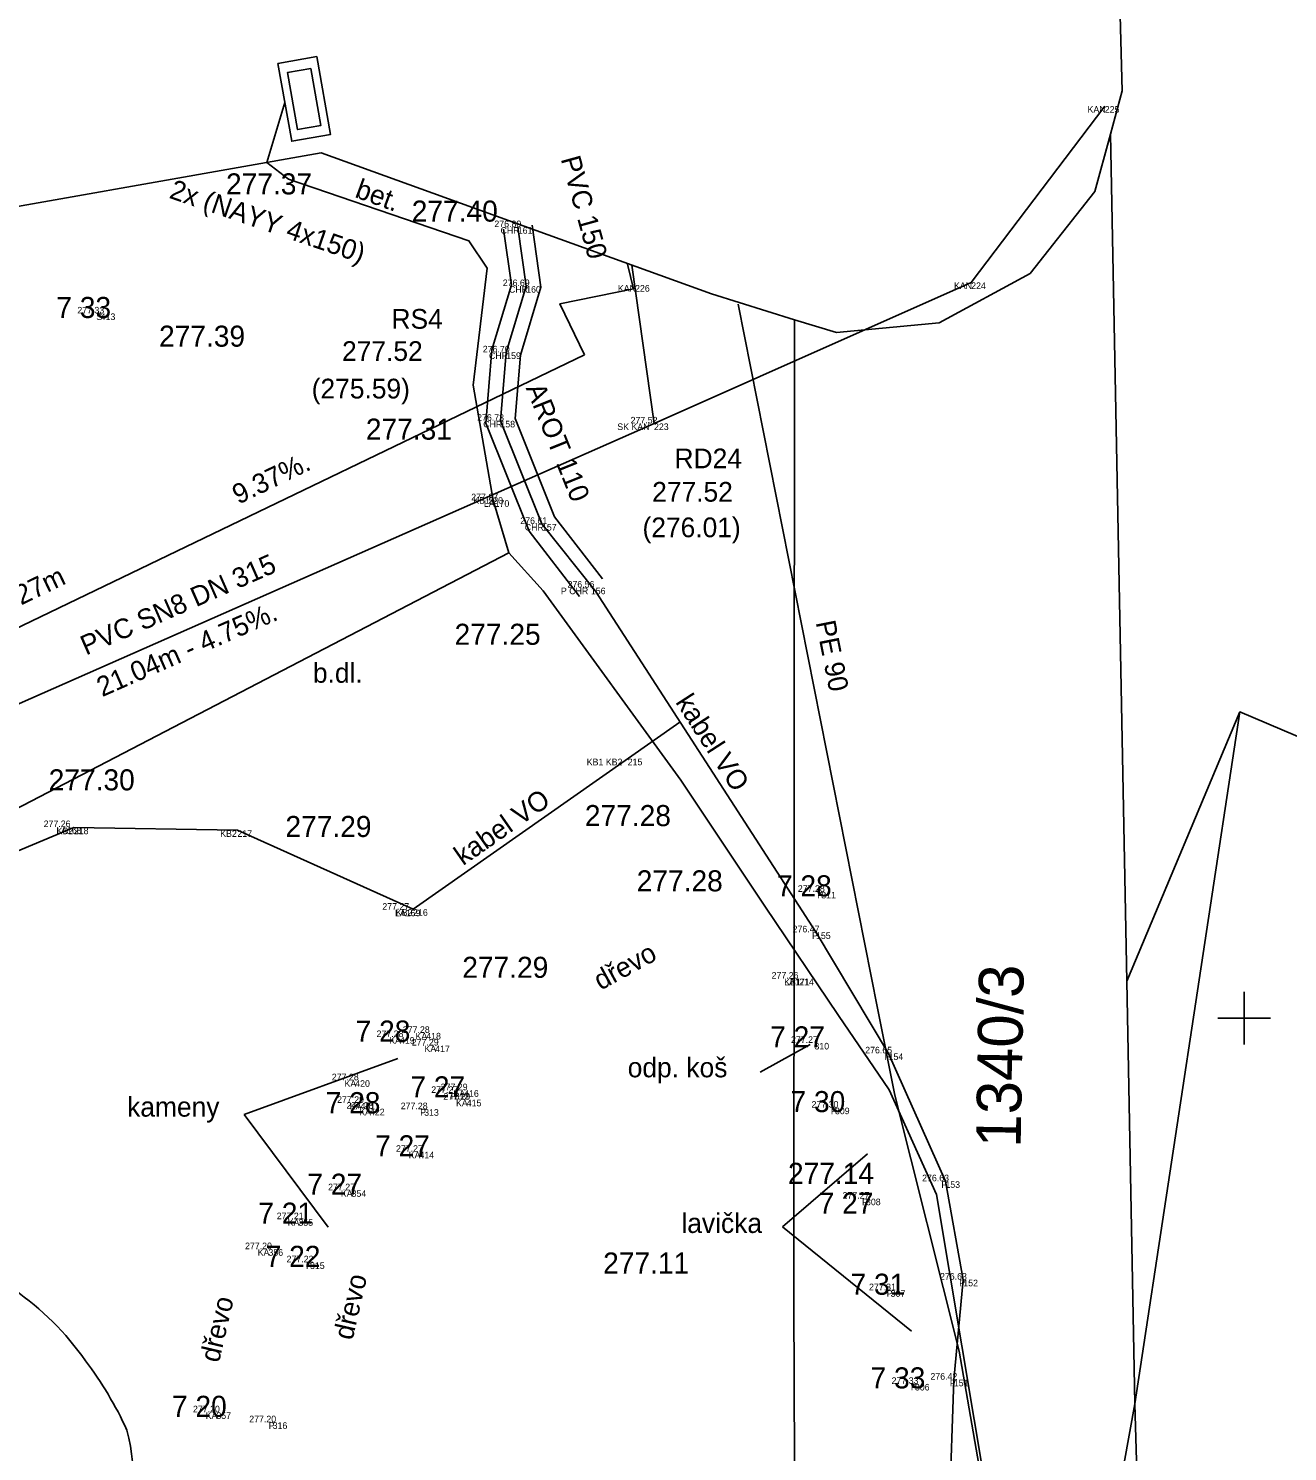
# Model space of a CAD drawing. Extents: x -601602 to -600882, y -1162594 to -1161950.
# Drawn here: x -601173.11 to -601149.18, y -1162033.24 to -1162006.19 of the extents above; entities that cross this region are included whole.
import ezdxf

# ---------------------------------------------------------------- set-up
doc = ezdxf.new("R2010")
doc.units = 0
for name, color, linetype in [('BODY', 7, 'Continuous'), ('BODY_CISLA', 7, 'Continuous'), ('BODY_KODY', 7, 'Continuous'), ('BODY_VYSKY_CELE', 7, 'Continuous'), ('G_TEXTY', 7, 'Continuous'), ('H_KOTY_VYSKOVE', 7, 'Continuous'), ('H_VYSKY_PREVZATE', 7, 'Continuous'), ('IS_CHRÁNIČKY', 7, 'Continuous'), ('IS_EON_NN', 7, 'Continuous'), ('IS_KAN_SPLASKOVA', 7, 'Continuous'), ('IS_ODVODNENI_HDV', 7, 'Continuous'), ('IS_ODVODNĚNÍ', 7, 'Continuous'), ('IS_VO_AREAL', 7, 'Continuous'), ('IS_VODOVOD', 7, 'Continuous'), ('KN_Hranice parcel', 7, 'Continuous'), ('KN_Parcelní čísla', 7, 'Continuous'), ('KN_Vnitřní kresba', 7, 'Continuous'), ('X_SOUR_KRIZKY_SEVER', 7, 'Continuous')]:
    doc.layers.add(name, color=color, linetype=linetype)

# ---------------------------------------------------------------- blocks, each defined once
blk = doc.blocks.new('POINT_DISPLAY')
blk.add_line((0, 0), (0, 0))
blk = doc.blocks.new('132_9')
at = {"layer": 'IS_EON_NN'}
for points in [[(-1.5, 1.5), (1.5, 1.5), (1.5, 0), (-1.5, 0)], [(-1.1, 1.2), (1.1, 1.2), (1.1, 0.3), (-1.1, 0.3)]]:
    blk.add_lwpolyline(points, close=True, dxfattribs=at)

msp = doc.modelspace()

# ---------------------------------------------------------------- linework, layer by layer
at = {"layer": 'G_TEXTY'}
for p, q in [((-601159.199, -1162026.027), (-601158.249, -1162025.499)), ((-601169.011, -1162026.832), (-601166.092, -1162025.768)), ((-601169.011, -1162026.832), (-601167.416, -1162028.971)), ((-601157.161, -1162027.579), (-601158.777, -1162028.963)), ((-601158.777, -1162028.963), (-601156.322, -1162030.951))]:
    msp.add_line(p, q, dxfattribs=at)
at = {"layer": 'IS_CHRÁNIČKY'}
for points in [[(-601162.202, -1162016.652), (-601163.109, -1162015.472), (-601163.86, -1162013.608), (-601163.758, -1162012.402), (-601163.369, -1162011.111), (-601163.538, -1162009.931)], [(-601162.638, -1162016.988), (-601163.591, -1162015.748), (-601164.42, -1162013.692), (-601164.302, -1162012.298), (-601163.931, -1162011.069), (-601164.082, -1162010.009)]]:
    msp.add_lwpolyline(points, dxfattribs=at)
at = {"layer": 'IS_EON_NN'}
for points in [[(-601168.24, -1162007.6), (-601168.58, -1162008.74), (-601168.17, -1162009.06), (-601164.74, -1162010.23), (-601164.39, -1162010.75), (-601164.66, -1162012.97), (-601164.28, -1162015.16), (-601163.98, -1162016.16)], [(-601173.65, -1162020.94), (-601173.38, -1162021.04), (-601163.98, -1162016.16)], [(-601163.98, -1162016.16), (-601163.33, -1162016.88), (-601160.71, -1162020.48), (-601159.11, -1162022.87), (-601157.71, -1162024.95), (-601156.75, -1162026.36), (-601155.85, -1162028.35), (-601154.65, -1162035.5), (-601155.01, -1162041.12), (-601155.31, -1162044.77), (-601156.69, -1162049.18), (-601157.91, -1162051.3), (-601160.19, -1162054.43), (-601160.24, -1162054.96), (-601159.53, -1162057.02), (-601158.24, -1162061.13), (-601156.45, -1162065.9)]]:
    msp.add_lwpolyline(points, dxfattribs=at)
at = {"layer": 'IS_KAN_SPLASKOVA'}
for points in [[(-601162.543, -1162012.396), (-601163.01, -1162011.424), (-601161.61, -1162011.139), (-601161.724, -1162010.674)], [(-601184.326, -1162054.364), (-601187.478, -1162047.498), (-601187.521, -1162033.934), (-601180.812, -1162021.187), (-601162.543, -1162012.396)]]:
    msp.add_lwpolyline(points, dxfattribs=at)
at = {"layer": 'IS_ODVODNENI_HDV'}
msp.add_line((-601161.22, -1162013.7), (-601180.4, -1162022.16), dxfattribs=at)
for centre, radius, start, end in [((-601176.384, -1162034.532), 5.3, 34.7611, 76.4254), ((-601177.686, -1162035.791), 7.094, 24.6751, 37.1246), ((-601173.973, -1162033.607), 2.841, 326.6304, 15.8773)]:
    msp.add_arc(centre, radius, start, end, dxfattribs=at)
at = {"layer": 'IS_ODVODNĚNÍ'}
for points in [[(-601161.22, -1162013.7), (-601155.19, -1162011.02), (-601152.65, -1162007.67)], [(-601161.639, -1162010.695), (-601161.22, -1162013.7)]]:
    msp.add_lwpolyline(points, dxfattribs=at)
at = {"layer": 'IS_VO_AREAL'}
for points in [[(-601164.95, -1162058.87), (-601164.15, -1162057.56), (-601163.04, -1162056.17), (-601161.14, -1162054.03), (-601158.99, -1162051.22), (-601157.56, -1162048.96), (-601156.33, -1162045.65), (-601156.093, -1162044.563), (-601155.26, -1162040.45), (-601155.6, -1162034.28), (-601155.52, -1162031.87), (-601155.34, -1162029.97), (-601155.68, -1162028.1), (-601156.76, -1162025.67), (-601158.14, -1162023.37), (-601162.335, -1162016.886), (-601163.35, -1162015.61), (-601164.14, -1162013.65), (-601164.03, -1162012.35), (-601163.65, -1162011.09), (-601163.81, -1162009.97)], [(-601160.726, -1162019.373), (-601165.8, -1162022.93), (-601169.14, -1162021.43), (-601172.25, -1162021.38), (-601174.81, -1162022.45)]]:
    msp.add_lwpolyline(points, dxfattribs=at)
at = {"layer": 'IS_VODOVOD'}
msp.add_lwpolyline([(-601173.453, -1162076.323), (-601173.346, -1162075.998), (-601173.532, -1162075.454), (-601180.753, -1162069.349), (-601179.01, -1162062.743), (-601175.747, -1162061.656), (-601172.447, -1162060.451), (-601167.292, -1162058.586), (-601162.43, -1162056.641), (-601160.803, -1162054.849), (-601159.903, -1162053.41), (-601158.77, -1162051.508), (-601157.252, -1162048.634), (-601156.804, -1162047.317), (-601155.861, -1162044.019), (-601155.023, -1162041.098), (-601154.828, -1162039.298), (-601154.638, -1162035.819), (-601155.419, -1162031.331), (-601156.644, -1162026.466), (-601156.968, -1162024.813), (-601159.618, -1162011.435)], dxfattribs=at)
at = {"layer": 'KN_Hranice parcel'}
msp.add_line((-601151, -1162065.68), (-601152.08, -1162032.33), dxfattribs=at)
for points in [[(-601193.7, -1161998.44), (-601190.9, -1161996.41), (-601187.36, -1161994.22), (-601184.31, -1161992.6), (-601181.51, -1161998.24), (-601169.5, -1161996.06), (-601163.7, -1161991.19), (-601161.68, -1161989.7), (-601159.76, -1161989.18), (-601157.82, -1161989.47), (-601156.15, -1161990.5), (-601155.03, -1161992.12), (-601152.53, -1161999.49), (-601152.32, -1162007.38), (-601152.54, -1162008.2)], [(-601152.54, -1162008.2), (-601152.84, -1162009.29), (-601154.07, -1162010.85), (-601155.8, -1162011.79), (-601157.75, -1162011.97), (-601158.55, -1162011.73)], [(-601152.08, -1162032.33), (-601152.23, -1162024.3), (-601152.54, -1162008.2)], [(-601158.55, -1162011.73), (-601160.13, -1162011.24), (-601167.55, -1162008.56), (-601175.66, -1162009.99), (-601173.72, -1162013.89), (-601177.28, -1162015.89), (-601179.96, -1162018), (-601181.89, -1162019.69), (-601183.72, -1162021.73), (-601185.22, -1162023.73), (-601186.78, -1162026.28), (-601188.51, -1162030.29), (-601189.34, -1162032.73), (-601190.11, -1162036.89)], [(-601158.55, -1162011.73), (-601158.56, -1162030.39), (-601158.54, -1162034.96), (-601158.53, -1162039.31), (-601158.48, -1162056.81), (-601158.01, -1162062.76), (-601156.16, -1162086.15)], [(-601152.08, -1162032.33), (-601150.08, -1162019.18), (-601140.6, -1162023.21), (-601143.34, -1162029.65), (-601109.34, -1162044.11), (-601106.6, -1162037.67), (-601101.21, -1162039.95)], [(-601152.08, -1162032.33), (-601157.63, -1162063.01), (-601151, -1162065.68)]]:
    msp.add_lwpolyline(points, dxfattribs=at)
at = {"layer": 'KN_Vnitřní kresba'}
msp.add_line((-601152.23, -1162024.3), (-601150.08, -1162019.18), dxfattribs=at)
at = {"layer": 'X_SOUR_KRIZKY_SEVER'}
for p, q in [((-601150, -1162025.5), (-601150, -1162024.5)), ((-601150.5, -1162025), (-601149.5, -1162025))]:
    msp.add_line(p, q, dxfattribs=at)

# ---------------------------------------------------------------- block references
at = {"layer": 'BODY'}
for p in [(-601152.65, -1162007.67), (-601163.81, -1162009.97), (-601161.58, -1162011.07), (-601155.19, -1162011.02), (-601163.65, -1162011.09), (-601171.74, -1162011.61), (-601164.03, -1162012.35), (-601164.14, -1162013.65), (-601161.22, -1162013.7), (-601164.37, -1162015.1), (-601164.25, -1162015.16), (-601163.35, -1162015.61), (-601162.42, -1162016.82), (-601161.72, -1162020.07), (-601172.38, -1162021.37), (-601172.25, -1162021.38), (-601169.14, -1162021.43), (-601158.04, -1162022.6), (-601165.94, -1162022.94), (-601165.8, -1162022.93), (-601158.14, -1162023.37), (-601158.54, -1162024.25), (-601158.46, -1162024.25), (-601166.05, -1162025.36), (-601165.55, -1162025.28), (-601165.38, -1162025.52), (-601158.17, -1162025.47), (-601156.76, -1162025.67), (-601166.9, -1162026.18), (-601165.01, -1162026.42), (-601164.83, -1162026.37), (-601166.8, -1162026.61), (-601166.62, -1162026.72), (-601165.59, -1162026.73), (-601164.78, -1162026.55), (-601157.78, -1162026.7), (-601165.68, -1162027.54), (-601155.68, -1162028.1), (-601166.97, -1162028.27), (-601157.19, -1162028.43), (-601167.98, -1162028.82), (-601168.55, -1162029.39), (-601167.76, -1162029.64), (-601155.34, -1162029.97), (-601156.72, -1162030.17), (-601155.52, -1162031.87), (-601156.26, -1162031.95), (-601169.54, -1162032.49), (-601168.47, -1162032.68)]:
    msp.add_blockref('POINT_DISPLAY', p, dxfattribs=at)
at = {"layer": 'IS_EON_NN', "xscale": 0.5, "yscale": 0.5, "rotation": -79.90249561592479}
msp.add_blockref('132_9', (-601168.24, -1162007.6), dxfattribs=at)

# ---------------------------------------------------------------- texts
at = {"layer": 'BODY_CISLA'}
for s, p in [('225', (-601152.65, -1162007.795)), ('161', (-601163.81, -1162010.095)), ('226', (-601161.58, -1162011.195)), ('224', (-601155.19, -1162011.145)), ('160', (-601163.65, -1162011.215)), ('413', (-601171.74, -1162011.735)), ('159', (-601164.03, -1162012.475)), ('158', (-601164.14, -1162013.775)), ('223', (-601161.22, -1162013.825)), ('220', (-601164.37, -1162015.225)), ('170', (-601164.25, -1162015.285)), ('157', (-601163.35, -1162015.735)), ('156', (-601162.42, -1162016.945)), ('215', (-601161.72, -1162020.195)), ('168', (-601172.38, -1162021.495)), ('218', (-601172.25, -1162021.505)), ('217', (-601169.14, -1162021.555)), ('311', (-601158.04, -1162022.725)), ('169', (-601165.94, -1162023.065)), ('216', (-601165.8, -1162023.055)), ('155', (-601158.14, -1162023.495)), ('171', (-601158.54, -1162024.375)), ('214', (-601158.46, -1162024.375)), ('419', (-601166.05, -1162025.485)), ('418', (-601165.55, -1162025.405)), ('417', (-601165.38, -1162025.645)), ('310', (-601158.17, -1162025.595)), ('154', (-601156.76, -1162025.795)), ('420', (-601166.9, -1162026.305)), ('312', (-601165.01, -1162026.545)), ('416', (-601164.83, -1162026.495)), ('421', (-601166.8, -1162026.735)), ('422', (-601166.62, -1162026.845)), ('313', (-601165.59, -1162026.855)), ('415', (-601164.78, -1162026.675)), ('309', (-601157.78, -1162026.825)), ('414', (-601165.68, -1162027.665)), ('153', (-601155.68, -1162028.225)), ('354', (-601166.97, -1162028.395)), ('308', (-601157.19, -1162028.555)), ('355', (-601167.98, -1162028.945)), ('356', (-601168.55, -1162029.515)), ('315', (-601167.76, -1162029.765)), ('152', (-601155.34, -1162030.095)), ('307', (-601156.72, -1162030.295)), ('151', (-601155.52, -1162031.995)), ('306', (-601156.26, -1162032.075)), ('357', (-601169.54, -1162032.615)), ('316', (-601168.47, -1162032.805))]:
    msp.add_text(s, height=0.125, dxfattribs=at).set_placement(p)
at = {"layer": 'BODY_KODY'}
for s, p in [('KAN', (-601152.977, -1162007.795)), ('CHR', (-601164.137, -1162010.095)), ('KAN', (-601161.907, -1162011.195)), ('KAN', (-601155.517, -1162011.145)), ('CHR', (-601163.977, -1162011.215)), ('S', (-601171.821, -1162011.735)), ('CHR', (-601164.357, -1162012.475)), ('CHR', (-601164.467, -1162013.775)), ('SK KAN', (-601161.918, -1162013.825)), ('KB1', (-601164.656, -1162015.225)), ('LA', (-601164.454, -1162015.285)), ('CHR', (-601163.677, -1162015.735)), ('P CHR', (-601162.99, -1162016.945)), ('KB1 KB2', (-601162.499, -1162020.195)), ('LA', (-601172.584, -1162021.495)), ('KB2', (-601172.577, -1162021.505)), ('KB2', (-601169.467, -1162021.555)), ('P', (-601158.116, -1162022.725)), ('LA', (-601166.144, -1162023.065)), ('KB2', (-601166.127, -1162023.055)), ('P', (-601158.216, -1162023.495)), ('KB1', (-601158.746, -1162024.375)), ('LA', (-601158.744, -1162024.375)), ('KA', (-601166.254, -1162025.485)), ('KA', (-601165.754, -1162025.405)), ('KA', (-601165.584, -1162025.645)), ('P', (-601156.836, -1162025.795)), ('KA', (-601167.104, -1162026.305)), ('P', (-601165.086, -1162026.545)), ('KA', (-601165.034, -1162026.495)), ('KA', (-601167.004, -1162026.735)), ('KA', (-601166.824, -1162026.845)), ('P', (-601165.666, -1162026.855)), ('KA', (-601164.984, -1162026.675)), ('P', (-601157.856, -1162026.825)), ('KA', (-601165.884, -1162027.665)), ('P', (-601155.756, -1162028.225)), ('KA', (-601167.174, -1162028.395)), ('P', (-601157.266, -1162028.555)), ('KA', (-601168.184, -1162028.945)), ('KA', (-601168.754, -1162029.515)), ('P', (-601167.836, -1162029.765)), ('P', (-601155.416, -1162030.095)), ('P', (-601156.796, -1162030.295)), ('P', (-601155.596, -1162031.995)), ('P', (-601156.336, -1162032.075)), ('KA', (-601169.744, -1162032.615)), ('P', (-601168.546, -1162032.805))]:
    msp.add_text(s, height=0.125, dxfattribs=at).set_placement(p)
at = {"layer": 'BODY_VYSKY_CELE'}
for s, p in [('276.80 ', (-601164.255, -1162009.97)), ('276.69 ', (-601164.095, -1162011.09)), ('277.33 ', (-601172.183, -1162011.61)), ('276.70 ', (-601164.475, -1162012.35)), ('276.73 ', (-601164.583, -1162013.65)), ('277.52 ', (-601161.665, -1162013.7)), ('277.27 ', (-601164.695, -1162015.16)), ('276.61 ', (-601163.762, -1162015.61)), ('276.56 ', (-601162.864, -1162016.82)), ('277.26 ', (-601172.824, -1162021.37)), ('277.28 ', (-601158.485, -1162022.6)), ('277.27 ', (-601166.385, -1162022.94)), ('276.47 ', (-601158.585, -1162023.37)), ('277.26 ', (-601158.984, -1162024.25)), ('277.28 ', (-601166.495, -1162025.36)), ('277.28 ', (-601165.995, -1162025.28)), ('277.29 ', (-601165.825, -1162025.52)), ('277.27 ', (-601158.615, -1162025.47)), ('276.65 ', (-601157.205, -1162025.67)), ('277.28 ', (-601167.345, -1162026.18)), ('277.29 ', (-601167.245, -1162026.61)), ('277.27 ', (-601165.455, -1162026.42)), ('277.29 ', (-601165.275, -1162026.37)), ('277.29 ', (-601165.225, -1162026.55)), ('277.28 ', (-601167.065, -1162026.72)), ('277.28 ', (-601166.035, -1162026.73)), ('277.30 ', (-601158.225, -1162026.7)), ('277.27 ', (-601166.125, -1162027.54)), ('276.63 ', (-601156.123, -1162028.1)), ('277.27 ', (-601167.415, -1162028.27)), ('277.27 ', (-601157.635, -1162028.43)), ('277.21 ', (-601168.392, -1162028.82)), ('277.20 ', (-601168.995, -1162029.39)), ('277.22 ', (-601168.205, -1162029.64)), ('276.63 ', (-601155.783, -1162029.97)), ('277.31 ', (-601157.132, -1162030.17)), ('277.33 ', (-601156.703, -1162031.95)), ('276.42 ', (-601155.965, -1162031.87)), ('277.20 ', (-601169.985, -1162032.49)), ('277.20 ', (-601168.915, -1162032.68))]:
    msp.add_text(s, height=0.125, dxfattribs=at).set_placement(p)
at = {"layer": 'G_TEXTY'}
for s, rotation, p in [('bet.', 339.9454, (-601166.926, -1162009.394)), ('AROT 110', 291.9525, (-601163.661, -1162013.027)), ('dřevo', 28.7255, (-601162.235, -1162024.479)), ('dřevo', 77.0269, (-601166.953, -1162031.133)), ('dřevo', 76.8541, (-601169.492, -1162031.56))]:
    msp.add_text(s, height=0.375, rotation=rotation, dxfattribs=at).set_placement(p)
for s, p in [('b.dl.', (-601167.705, -1162018.627)), ('odp. koš', (-601161.72, -1162026.124)), ('kameny', (-601171.237, -1162026.872)), ('lavička', (-601160.699, -1162029.082))]:
    msp.add_text(s, height=0.375, dxfattribs=at).set_placement(p)
at = {"layer": 'H_KOTY_VYSKOVE'}
for s, p in [(' 7 33', (-601172.731, -1162011.696)), (' 7 28', (-601159.031, -1162022.686)), (' 7 28', (-601167.041, -1162025.446)), (' 7 27', (-601159.16, -1162025.556)), (' 7 27', (-601166, -1162026.506)), (' 7 28', (-601167.611, -1162026.806)), (' 7 30', (-601158.773, -1162026.786)), (' 7 27', (-601166.67, -1162027.626)), (' 7 27', (-601167.96, -1162028.356)), (' 7 27', (-601158.238, -1162028.717)), (' 7 21', (-601168.891, -1162028.906)), (' 7 22', (-601168.751, -1162029.726)), (' 7 31', (-601157.631, -1162030.256)), (' 7 33', (-601157.251, -1162032.036)), (' 7 20', (-601170.533, -1162032.576))]:
    msp.add_text(s, height=0.4, dxfattribs=at).set_placement(p)
at = {"layer": 'H_VYSKY_PREVZATE'}
for s, p in [('277.37', (-601169.357, -1162009.348)), ('277.40', (-601165.826, -1162009.865)), ('277.39', (-601170.63, -1162012.241)), ('277.31', (-601166.698, -1162014.008)), ('277.25', (-601165.011, -1162017.906)), ('277.30', (-601172.728, -1162020.672)), ('277.28', (-601162.534, -1162021.351)), ('277.29', (-601168.227, -1162021.558)), ('277.28', (-601161.549, -1162022.591)), ('277.29', (-601164.865, -1162024.234)), ('277.14', (-601158.673, -1162028.149)), ('277.11', (-601162.187, -1162029.853))]:
    msp.add_text(s, height=0.4, dxfattribs=at).set_placement(p)
at = {"layer": 'IS_EON_NN'}
msp.add_text('2x (NAYY 4x150)', height=0.375, rotation=341.1651, dxfattribs=at).set_placement((-601170.456, -1162009.41))
at = {"layer": 'IS_KAN_SPLASKOVA'}
for s, rotation, p in [('PVC 150', 285.4685, (-601162.995, -1162008.672)), ('9.37%.', 25.6968, (-601169.122, -1162015.244)), ('20.27m', 25.6968, (-601173.882, -1162017.462))]:
    msp.add_text(s, height=0.375, rotation=rotation, dxfattribs=at).set_placement(p)
for s, p in [('RS4', (-601166.211, -1162011.9)), ('277.52', (-601167.151, -1162012.512)), ('(275.59)', (-601167.728, -1162013.225))]:
    msp.add_text(s, height=0.375, dxfattribs=at).set_placement(p)
at = {"layer": 'IS_ODVODNENI_HDV'}
for s, p in [('RD24', (-601160.83, -1162014.552)), ('277.52', (-601161.255, -1162015.186)), ('(276.01)', (-601161.439, -1162015.862))]:
    msp.add_text(s, height=0.375, dxfattribs=at).set_placement(p)
for s, p in [('PVC SN8 DN 315', (-601172.019, -1162018.112)), ('21.04m - 4.75%.', (-601171.711, -1162018.902))]:
    msp.add_text(s, height=0.375, rotation=23.7136, dxfattribs=at).set_placement(p)
at = {"layer": 'IS_VO_AREAL'}
for rotation, p in [(302.9023, (-601160.822, -1162018.995)), (35.0297, (-601164.851, -1162022.112))]:
    msp.add_text('kabel VO', height=0.375, rotation=rotation, dxfattribs=at).set_placement(p)
at = {"layer": 'IS_VODOVOD'}
msp.add_text('PE 90', height=0.375, rotation=281.2045, dxfattribs=at).set_placement((-601158.147, -1162017.479))
at = {"layer": 'KN_Parcelní čísla'}
msp.add_text('1340/3', height=0.85, rotation=89, dxfattribs=at).set_placement((-601154.25, -1162027.464))

doc.saveas('drawing.dxf')
